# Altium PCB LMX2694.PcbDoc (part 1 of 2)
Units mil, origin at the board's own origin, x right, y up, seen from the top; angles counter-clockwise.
Board outline 2500 x 2200 mil, 4 copper layers (Top Layer, RF GND, Signal GND, Bottom Layer), stack 60.6 mil thick; 109 components, 60 nets, 306 pads, 206 vias.
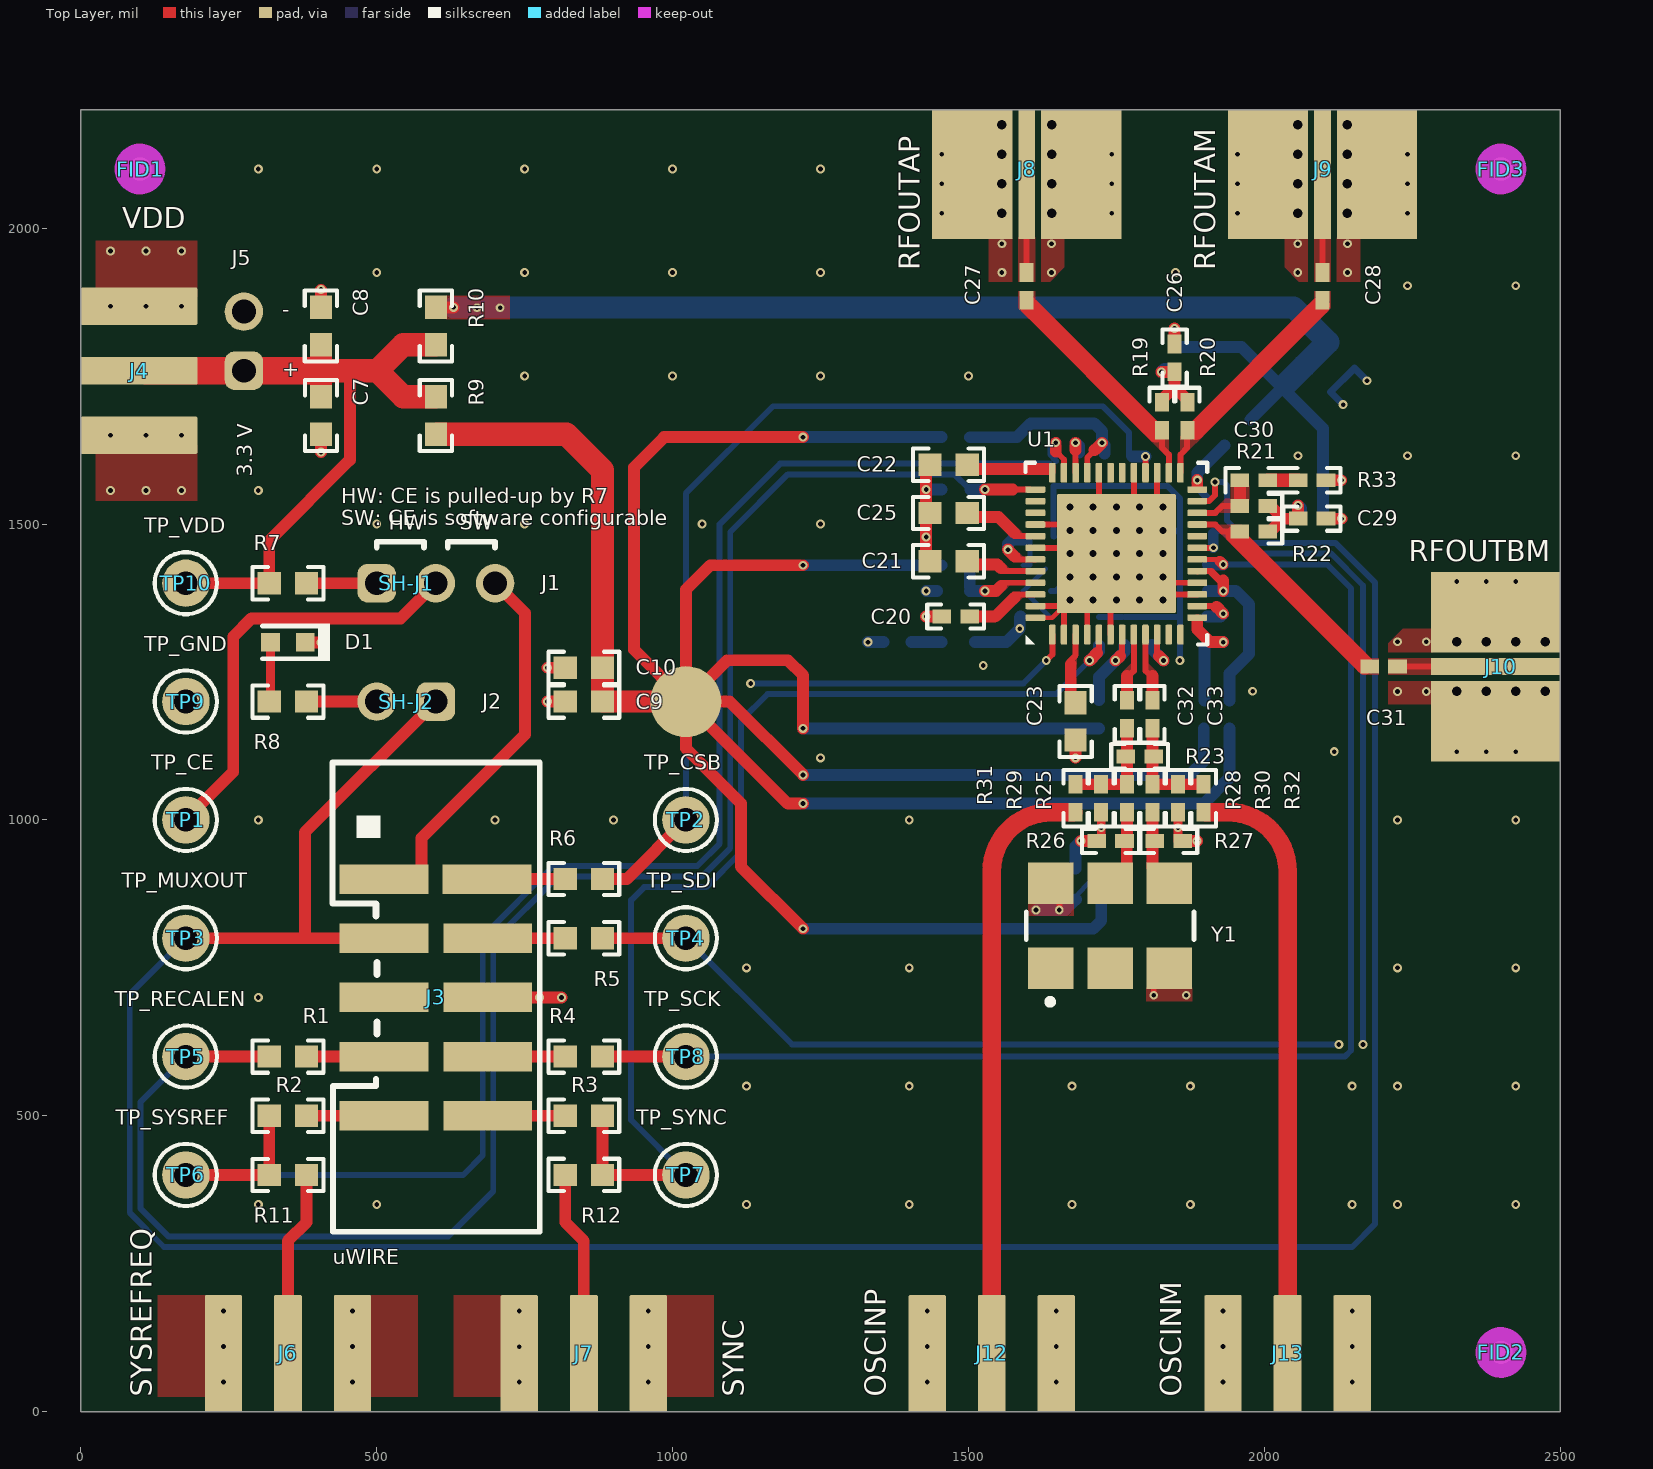
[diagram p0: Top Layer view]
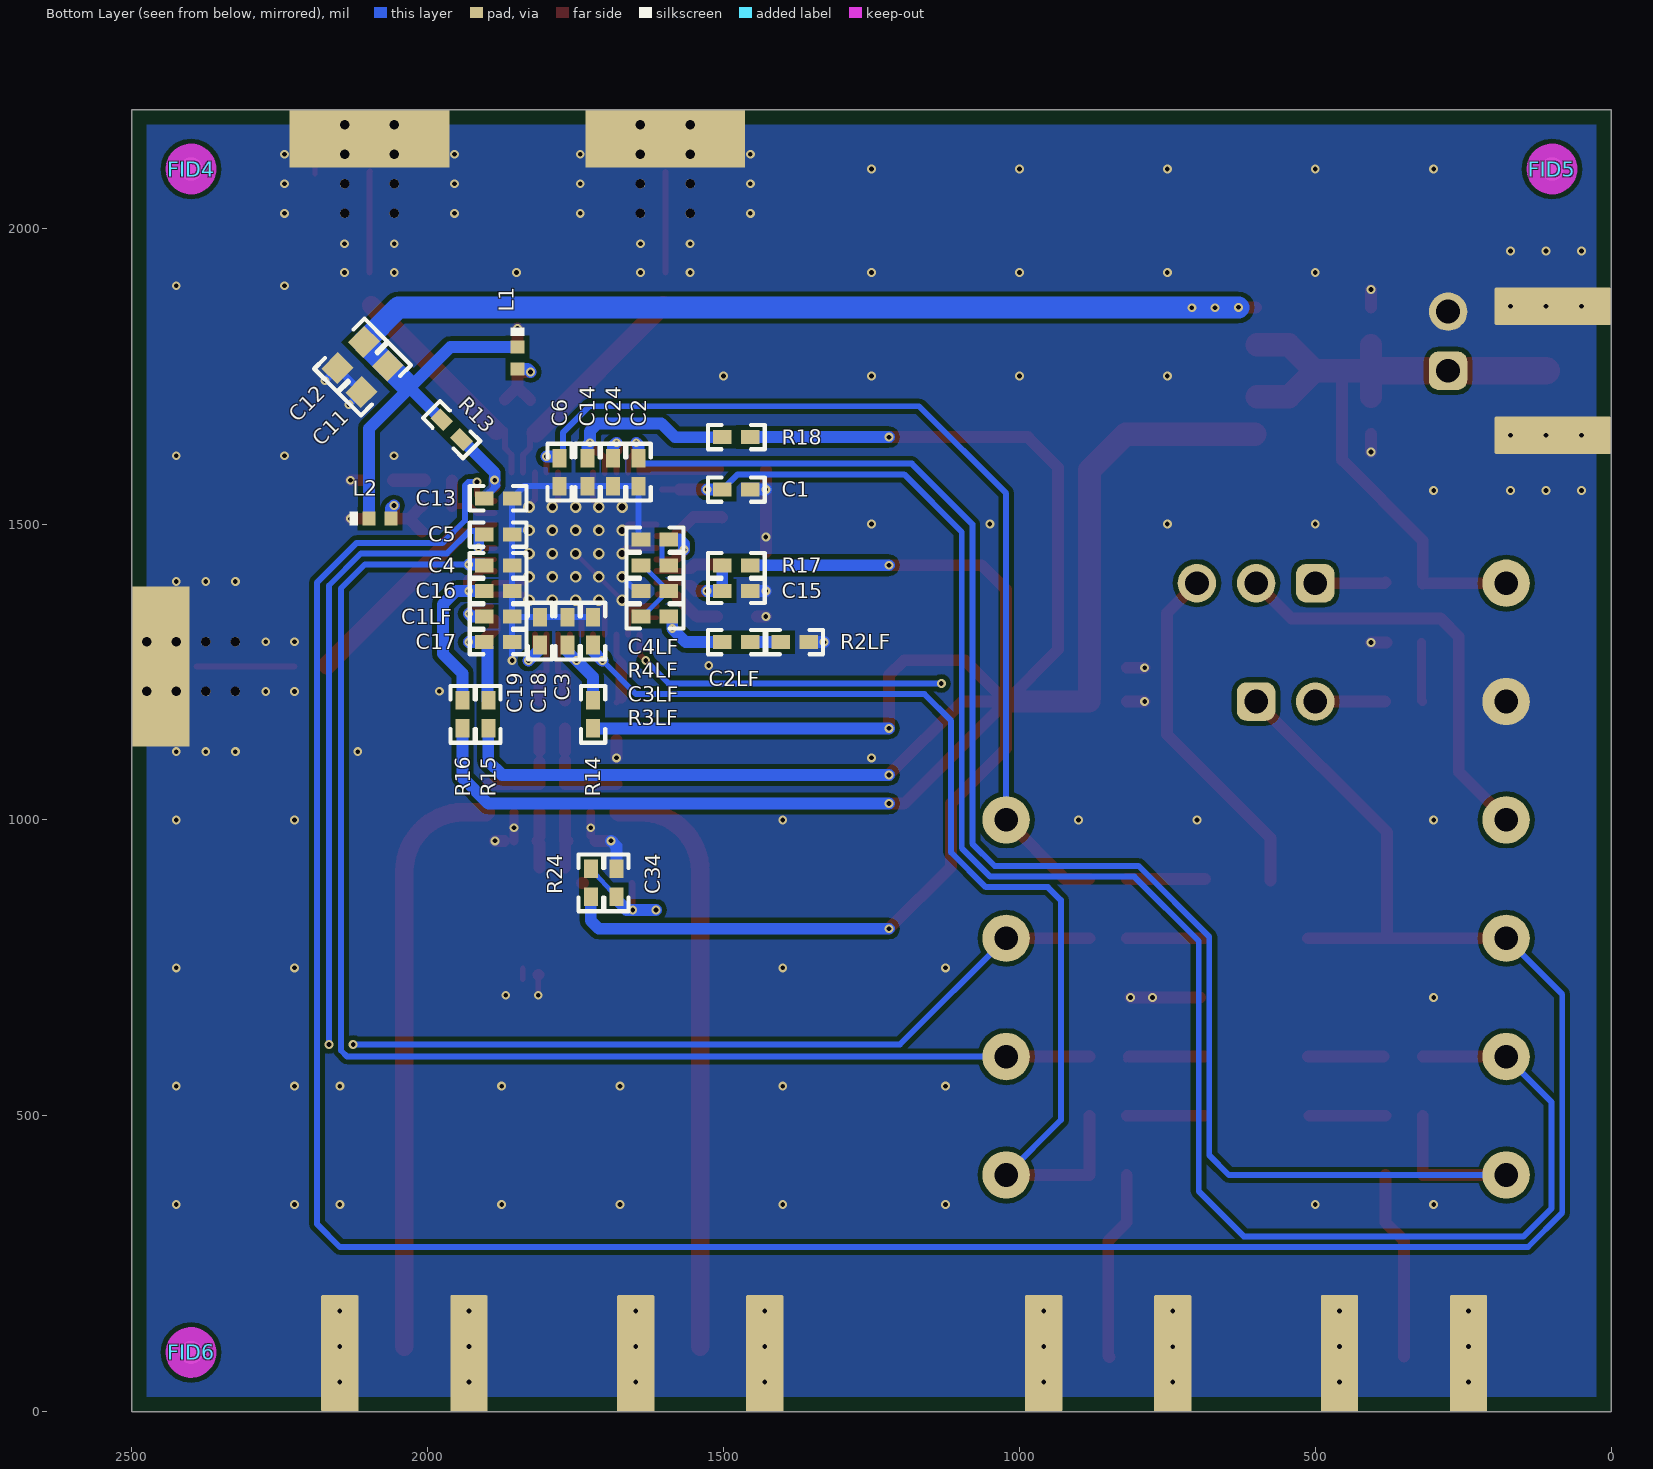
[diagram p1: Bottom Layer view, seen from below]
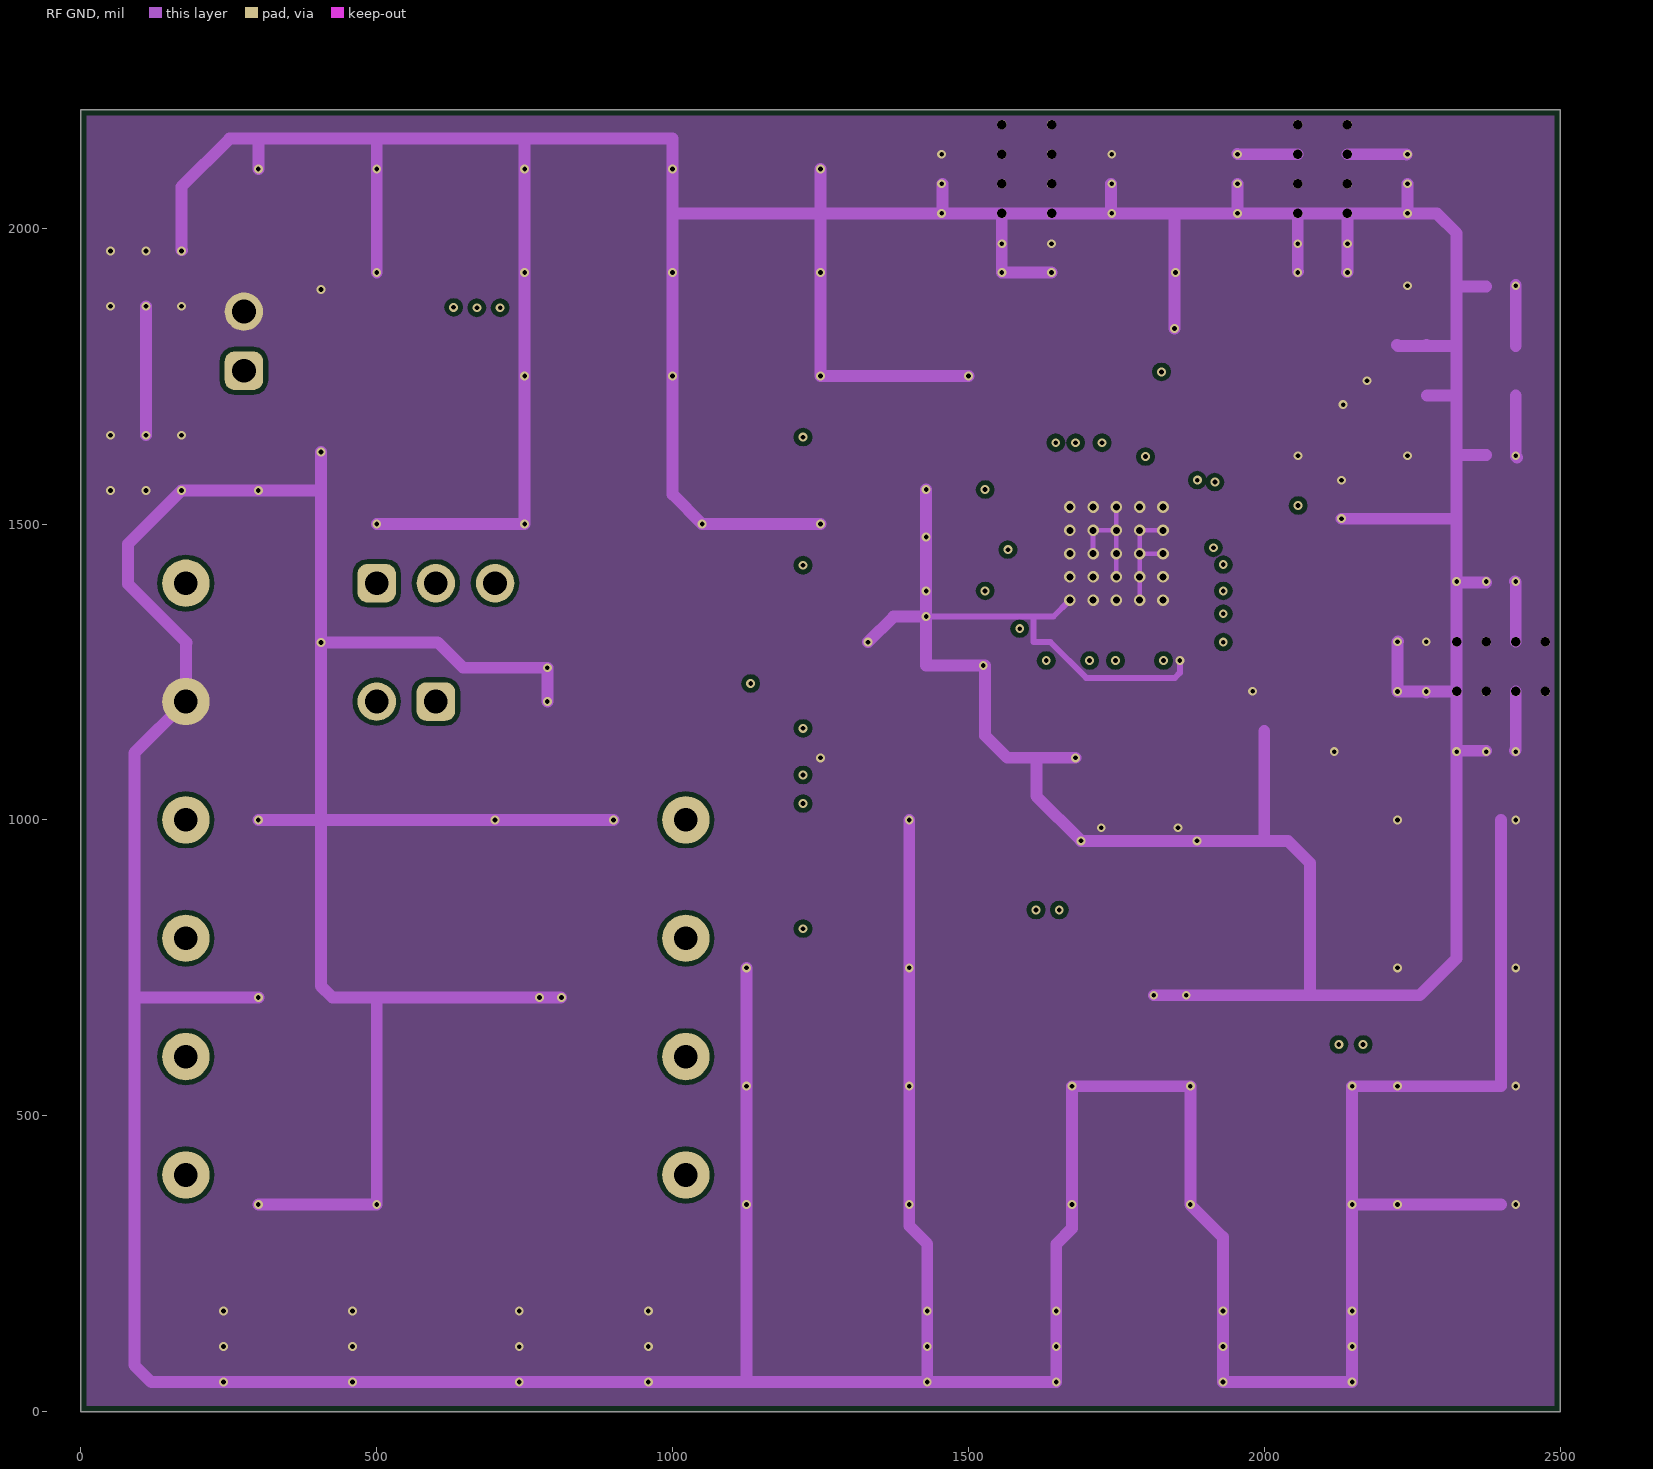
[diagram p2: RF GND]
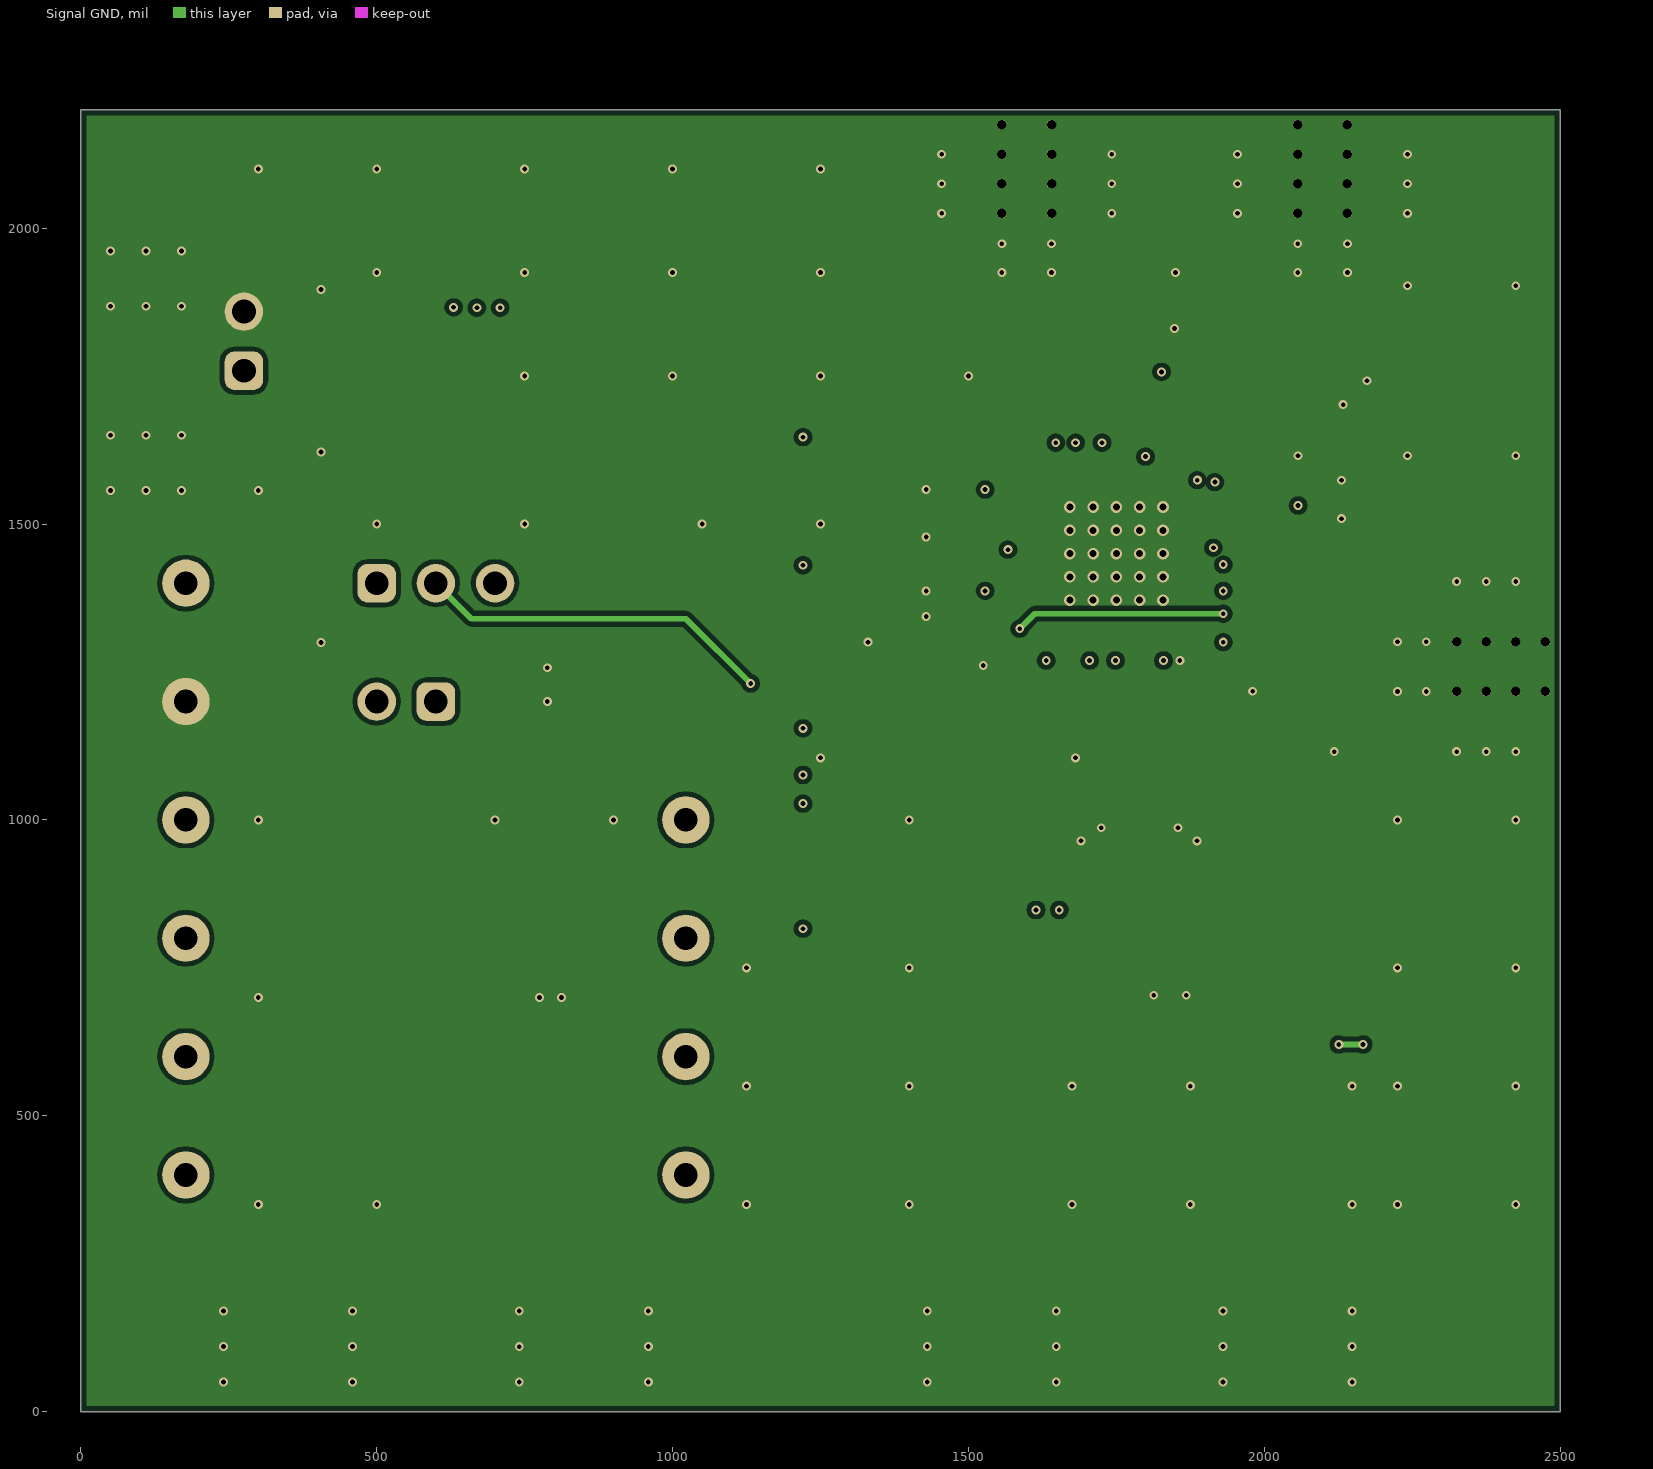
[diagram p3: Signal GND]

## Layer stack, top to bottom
Top Solder: solder mask 0.4, Solder Resist, Dk 3.5
Top Layer: signal copper 1.4
Dielectric1: core 16, Rogers RO4350B, Dk 3.66
RF GND: signal copper 1.4
Dielectric 2: dielectric 23, FR4, Dk 4.2
Signal GND: signal copper 1.4
Dielectric 3: dielectric 16, FR4, Dk 4.2
Bottom Layer: signal copper 1.4
Bottom Solder: solder mask 0.4, Solder Resist, Dk 3.5

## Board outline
0,0 0,2200 2500,2200 2500,0

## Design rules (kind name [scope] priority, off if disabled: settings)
AcuteAngle [All] p1: minimum=4.50000000000000E+0001 checktracksonly=FALSE
AssemblyTestPointUsage [All] p1: valid=2
BoardOutlineClearance BoardOutlineClearance_MountingHoles [OnCopper and InComponentClass('Mounting Holes')] p1: gap=39.37 ignorepadtopadclearanceinfootprint=FALSE
BoardOutlineClearance BoardOutlineClearance_Poly [OnCopper and IsPoly and not OnBottomLayer] p2: gap=25 ignorepadtopadclearanceinfootprint=FALSE except(10: Poly-OutlineEdge)
BoardOutlineClearance BoardOutlineClearance_Poly_Bottom [OnCopper and IsPoly and OnBottomLayer] p3: gap=25 ignorepadtopadclearanceinfootprint=FALSE
BoardOutlineClearance [OnCopper and Not InComponentClass('Logo') and not InComponentClass('FiducialMark') and not InRegion(1000,500,4000,800) and not InPoly and not InComponent('RFOUTAP')and not InComponent('RFOUTAM')and not InComponent('RFOUTBP')and not InComponent('RFOUTBM')and not InComponent('OSCINP')and not InComponent('OSCINM')and not InComponent('SYSREFREQ')and not InComponent('SYNC')and not InComponent('VDD')and not IsPad] p4: gap=75 ignorepadtopadclearanceinfootprint=FALSE except(25: Track-OutlineEdge Via-OutlineEdge)
Clearance Clearance_Keepouts [((IsTrack Or IsArc) And Not InPoly) And IsFree and IsKeepOut vs ((IsTrack Or IsArc) And Not InPoly) And IsFree and IsKeepOut] p1: gap=0 ignorepadtopadclearanceinfootprint=FALSE
Clearance Clearance_Poly [InPolygon] p2: gap=10 ignorepadtopadclearanceinfootprint=TRUE except(7.87: Arc-Fill Arc-Poly Arc-Region Track-Fill Track-Poly Track-Region SMDPad-Fill SMDPad-Poly SMDPad-Region THPad-Fill THPad-Poly THPad-Region Via-Fill Via-Poly Via-Region Fill-Fill Fill-Poly Fill-Region Poly-Poly Poly-Region Region-Region)
Clearance Clearance_FiducialMark [IsKeepOut and InComponentClass('FiducialMark') vs IsPad and InComponentClass('FiducialMark')] p3: gap=0 ignorepadtopadclearanceinfootprint=FALSE
Clearance [All] p4: gap=7.87 ignorepadtopadclearanceinfootprint=TRUE
ComponentClearance ComponentClearance_MountingHoles_FiducialMarks [InComponentClass('Mounting Holes') vs InComponentClass('FiducialMark')] p1: gap=50 collisioncheckmode=3 verticalgap=10 showdistances=FALSE
ComponentClearance ComponentClearance_Shunt [InComponentClass('Header') vs InComponentClass('Shunt')] p2: gap=0 collisioncheckmode=3 verticalgap=0 showdistances=FALSE
ComponentClearance ComponentClearance_Logo [InComponentClass('Logo')] p3: gap=50 collisioncheckmode=3 verticalgap=10 showdistances=FALSE
ComponentClearance ComponentClearance_ScrewToNut [(HasFootprint('NY PMS 440 0025 PH')) vs (HasFootprint('Keystone_1902C'))] p4: gap=5 collisioncheckmode=3 verticalgap=10 showdistances=FALSE
ComponentClearance ComponentClearance_MountingHoles [InComponentClass('Mounting Holes')] p5: gap=250 collisioncheckmode=3 verticalgap=100000 showdistances=FALSE
ComponentClearance ComponentClearance_SmallPassives [HasFootprint('0201*') or HasFootprint('0402*') or HasFootprint('0508') or HasFootprint('0603*') or HasFootprint('0612') or HasFootprint('0805*') or HasFootprint('0815*') or HasFootprint('0830*') or HasFootprint('1206*') or HasFootprint('1210*') or HasFootprint('1808*') or HasFootprint('1812*') or HasFootprint('1825*') or HasFootprint('2010*') or HasFootprint('2220*') or HasFootprint('2225*') or HasFootprint('2512*') or HasFootprint('2728*') or HasFootprint('3518*') vs HasFootprint('0201*') or HasFootprint('0402*') or HasFootprint('0508') or HasFootprint('0603*') or HasFootprint('0612') or HasFootprint('0805*') or HasFootprint('0815*') or HasFootprint('0830*') or HasFootprint('1206*') or HasFootprint('1210*') or HasFootprint('1808*') or HasFootprint('1812*') or HasFootprint('1825*') or HasFootprint('2010*') or HasFootprint('2220*') or HasFootprint('2225*') or HasFootprint('2512*') or HasFootprint('2728*') or HasFootprint('3518*')] p6: gap=14.96 collisioncheckmode=3 verticalgap=10 showdistances=FALSE
ComponentClearance ComponentClearance_THtoSMT [IsThruComponent vs IsSMTComponent] p7: gap=40 collisioncheckmode=3 verticalgap=30 showdistances=FALSE
ComponentClearance ComponentClearance_THtoTH [IsThruComponent vs IsThruComponent] p8: gap=30 collisioncheckmode=3 verticalgap=30 showdistances=FALSE
ComponentClearance [All] p9: gap=30 collisioncheckmode=3 verticalgap=10 showdistances=FALSE
DiffPairsRouting [All] p1: maxlimit=100 minlimit=10 mostfreqgap=10 toplayer_minwidth=15 toplayer_maxwidth=15 toplayer_prefwidth=15 midlayer1_minwidth=15 midlayer1_maxwidth=15 midlayer1_prefwidth=15 midlayer2_minwidth=15 midlayer2_maxwidth=15 midlayer2_prefwidth=15 bottomlayer_minwidth=15 bottomlayer_maxwidth=15 bottomlayer_prefwidth=15 maxuncoupledlength=1000
FabricationTestPointUsage TestPointUsage [All] p1: valid=2 allowmultiple=FALSE
FabricationTestpoint Testpoint [All] p1: side=3 testpointundercomponent=TRUE minsize=40 maxsize=100 preferedsize=60 minholesize=0 maxholesize=40 preferedholesize=32 testpointgrid=1 allowsidetop=TRUE allowsidebottom=TRUE usegrid=TRUE gridtolerance=0.01
FanoutControl Fanout_LCC [IsLCC] p1: bgadir=Out bgaviamode=Centered fanoutstyle=Auto fanoutdirection=Alternating viagrid=1 // Fanout_LCC (Default Rule)
FanoutControl Fanout_BGA [IsBGA] p2: bgadir=Out bgaviamode=Centered fanoutstyle=Auto fanoutdirection=Alternating viagrid=1 // Fanout_BGA (Default Rule)
FanoutControl Fanout_Default [All] p4: bgadir=Out bgaviamode=Centered fanoutstyle=Auto fanoutdirection=Alternating viagrid=1 // Fanout_Default (Default Rule)
FanoutControl Fanout_Small [(CompPinCount < 5)] p5: bgadir=Out bgaviamode=Centered fanoutstyle=Auto fanoutdirection=OutThenIn viagrid=1 // Fanout_Small (Default Rule)
HoleSize [All] p1: absolutevalues=TRUE maxlimit=251 minlimit=7.87 maxpercent=80.000 minpercent=20.000
MinimumAnnularRing MinimumAnnularRing_ThermalPadVias [IsVia and InAnyComponent] p1: minimumring=3.94
MinimumAnnularRing [All] p2: minimumring=3.5
MinimumSolderMaskSliver MinimumSolderMaskSliver_ThermalVia [IsVia vs IsPad] p1: minsoldermaskwidth=0.79
MinimumSolderMaskSliver MinimumSolderMaskSliver_Logo [InComponentClass('Logo') vs InComponentClass('Logo')] p2: minsoldermaskwidth=0.7
MinimumSolderMaskSliver [All] p3: minsoldermaskwidth=3.94
PlaneConnect [All] p1: planeconnectstyle=Direct reliefexpansion=10 reliefentries=4 reliefconductorwidth=10 reliefairgap=10
PolygonConnect [All] p1: connectstyle=Direct reliefconductorwidth=10 reliefentries=4 polygonreliefangle="90 Angle" airgapwidth=10
RoutingVias ThermalPadVias [IsVia and InAnyComponent] p1: holewidth=7.87 width=19.68 viastyle="Through Hole" minholewidth=7.87 minwidth=19.68 maxholewidth=12.99 maxwidth=23.62
RoutingVias [All] p2: holewidth=13 width=25 viastyle="Through Hole" minholewidth=8 minwidth=15 maxholewidth=18 maxwidth=25
SilkToBoardRegionClearance [Not ((IsComment or IsDesignator) And (Hide <> 'False')) and not InRegion(1000,500,4000,800)] p1:
SilkToSilkClearance SilkToSilkClearance_Pb-FreeLogo [(HasFootprint('Pb-Free_Overlay_Medium') OR HasFootprint('Pb-Free_Overlay_Small')) vs (HasFootprint('Pb-Free_Overlay_Medium') OR HasFootprint('Pb-Free_Overlay_Small'))] p1: silktosilkclearance=0
SilkToSilkClearance [All] p2: silktosilkclearance=3.94
SilkToSolderMaskClearance SilkToComponentPadClearance [(IsPad or IsFill or IsRegion) and InAnycomponent] p1: minsilkscreentomaskgap=3.94 clearancetoexposedcopper=TRUE
SilkToSolderMaskClearance "Silk to Solder Mask Opening" [All] p2: minsilkscreentomaskgap=3 clearancetoexposedcopper=FALSE
SolderMaskExpansion [All] p1: expansion=1.97
Width [All] p1: maxlimit=100 minlimit=6 preferedwidth=10 checkconnectedcopper=TRUE
15 further rules are at their usual default settings.

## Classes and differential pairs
component class FiducialMark: FID1 FID2 FID3 FID4 FID5 FID6
component class LMX2694_HW: FID1 FID2 FID3 FID4 FID5 FID6 SH-J1 SH-J2
component class Header: J1 J2 J5
component class LMX2694_SYNTH: C1LF C2LF C3LF C4LF C13 C14 C15 C16 C17 C18 C19 C20 C21 C22 C23 C24 C25 C26 C27 C28 C29 C30 C31 C32 C33 C34 J8 J9 J10 J12 J13 L1 L2 R2LF R3LF R4LF R13 R14 R15 R16 R17 R18 R19 R20 R21 R22 R23 R24 R25 R26 R27 R28 R29 R30 R31 R32 R33 U1 Y1
component class Shunt: SH-J1 SH-J2

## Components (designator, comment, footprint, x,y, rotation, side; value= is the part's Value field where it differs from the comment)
C1 "885012005044" 0402 1478.35,1558.27 r180 bottom value=47pF
C1LF "C0402C471K5GAC7867" 0402 1880.91,1343.7 r180 bottom value=470pF
C2 "885012005044" 0402 1643.5,1587.6 r270 bottom value=47pF
C2LF "CGA2B3X7R1H683K050BB" 0402 1478.35,1300.39 r180 bottom value=0.068uF
C3 "885012005044" 0402 1720.47,1319.09 r90 bottom value=47pF
C3LF "885012005044" 0402 1615.94,1387.01 r0 bottom value=47pF
C4 "885012005044" 0402 1880.91,1430.32 r180 bottom value=47pF
C4LF "C0402C182J5RACTU" 0402 1615.94,1473.62 r0 bottom value=1800pF
C5 "885012005044" 0402 1880.91,1482.09 r180 bottom value=47pF
C6 "885012005044" 0402 1776.97,1587.6 r270 bottom value=47pF
C7 "885012206046" 0603 405.71,1683.46 r270 top value=0.1uF
C8 "GRM188R61A106KAALD" 0603 405.71,1834.65 r90 top value=10uF
C9 "885012206046" 0603 850,1200 r180 top value=0.1uF
C10 "GRM188R61A106KAALD" 0603 850,1257.09 r180 top value=10uF
C11 "885012206046" 0603 2089.79,1745.25 r315 bottom value=0.1uF
C12 "GRM188R61A106KAALD" 0603 2130.09,1785.66 r315 bottom value=10uF
C13 "885012205037" 0402 1880.91,1543.5 r180 bottom value=0.1uF
C14 "GRM155R61E105KA12D" 0402 1730.12,1587.6 r270 bottom value=1uF
C15 "GRM155R61E105KA12D" 0402 1478.35,1387.01 r180 bottom value=1uF
C16 "GRM155R61E105KA12D" 0402 1880.91,1387.01 r180 bottom value=1uF
C17 "GRM155R61E105KA12D" 0402 1880.91,1300.39 r180 bottom value=1uF
C18 "GRM155R61E105KA12D" 0402 1763.78,1319.09 r90 bottom value=1uF
C19 "GRM155R61E105KA12D" 0402 1810.04,1319.09 r90 bottom value=1uF
C20 "GRM155R61E105KA12D" 0402 1478.35,1343.7 r180 top value=1uF
C21 "GRM188R61A106KAALD" 0603 1466.54,1437.2 r180 top value=10uF
C22 "GRM188R61A106KAALD" 0603 1466.54,1600.2 r180 top value=10uF
C23 "GRM188R61A106KAALD" 0603 1681.1,1166.54 r270 top value=10uF
C24 "GRM155R61E105KA12D" 0402 1686.81,1587.6 r270 bottom value=1uF
C25 "GRM188R61A106KAALD" 0603 1466.54,1518.7 r180 top value=10uF
C26 "520L103KT16T" 0402_065 1848.43,1780.71 r270 top value=0.01uF
C27 "520L103KT16T" 0402_065 1598.43,1901.57 r270 top value=0.01uF
C28 "520L103KT16T" 0402_065 2098.43,1901.57 r270 top value=0.01uF
C29 "520L103KT16T" 0402_065 2080.71,1509.06 r180 top value=0.01uF
C30 "520L103KT16T" 0402_065 1982.28,1574.02 r180 top value=0.01uF
C31 "520L103KT16T" 0402_065 2201.57,1259.06 r180 top value=0.01uF
C32 "885012205037" 0402 1767.72,1178.35 r270 top value=0.1uF
C33 "885012205037" 0402 1811.02,1178.35 r270 top value=0.1uF
C34 "GRM155R61E105KA12D" 0402 1681.1,893.7 r90 bottom value=1uF
D1 "LTST-C190GKT" LED_LTST-C190 350,1300 r0 top value=Green
FID1 "Fiducial" Fiducial10-20 100,2100 r0 top
FID2 "Fiducial" Fiducial10-20 2400,100 r0 top
FID3 "Fiducial" Fiducial10-20 2400,2100 r0 top
FID4 "Fiducial" Fiducial10-20 2400,2100 r180 bottom
FID5 "Fiducial" Fiducial10-20 100,2100 r180 bottom
FID6 "Fiducial" Fiducial10-20 2400,100 r180 bottom
J1 "TSW-103-07-G-S" TSW-103-07-G-S 600,1400 r0 top
J2 "TSW-102-07-G-S" TSW-102-07-G-S 550,1200 r180 top
J3 "uWIRE" FCI_52601-S10-8LF 600,700 r0 top
J4 "VDD" FP-CON-SMA-EDGE-S_CONN_JACK-MFG -187.5,1759.06 r90 top
J5 "TSW-102-07-G-S" TSW-102-07-G-S 275.59,1809.06 r90 top
J6 "SYSREFREQ" FP-CON-SMA-EDGE-S_CONN_JACK-MFG 350,-187.5 r180 top
J7 "SYNC" FP-CON-SMA-EDGE-S_CONN_JACK-MFG 850,-187.5 r180 top
J8 "RFOUTAP" Johnson_142-0771-831 1598.43,2200 r0 top
J9 "RFOUTAM" Johnson_142-0771-831 2098.43,2200 r0 top
J10 "RFOUTBM" Johnson_142-0771-831 2500,1259.06 r270 top
J12 "OSCINP" FP-CON-SMA-EDGE-S_CONN_JACK-MFG 1539.37,-187.5 r180 top
J13 "OSCINM" FP-CON-SMA-EDGE-S_CONN_JACK-MFG 2039.37,-187.5 r180 top
L1 "LQG15HS18NJ02D" IND_LQG15H 1848.43,1780.71 r270 bottom value=18nH
L2 "LQG15HS18NJ02D" IND_LQG15H 2080.71,1509.06 r180 bottom value=18nH
R1 "CRCW060333R0JNEA" 0603 350,600 r0 top value=33
R2 "CRCW060333R0JNEA" 0603 350,500 r180 top value=33
R2LF "CRCW040268R1FKED" 0402 1379.92,1300.39 r0 bottom value=68.1
R3 "CRCW060333R0JNEA" 0603 850,500 r0 top value=33
R3LF "CRCW04020000Z0ED" 0402 1615.94,1343.7 r0 bottom value=0
R4 "CRCW060333R0JNEA" 0603 850,600 r0 top value=33
R4LF "CRCW040218R2FKED" 0402 1615.94,1430.32 r180 bottom value=18.2
R5 "CRCW060333R0JNEA" 0603 850,800 r0 top value=33
R6 "CRCW060333R0JNEA" 0603 850,900 r0 top value=33
R7 "CRCW06031K00JNEA" 0603 350,1400 r180 top value=1.0k
R8 "CRCW0603330RJNEA" 0603 350,1200 r180 top value=330
R9 "CRCW06030000Z0EA" 0603 600,1683.46 r270 top value=0
R10 "CRCW06030000Z0EA" 0603 600,1834.65 r90 top value=0
R11 "CRCW06030000Z0EA" 0603 350,400 r180 top value=0
R12 "CRCW06030000Z0EA" 0603 850,400 r0 top value=0
R13 "CRCW04020000Z0ED" 0402 1959.65,1659.65 r225 bottom value=0
R14 "CRCW04020000Z0ED" 0402 1720.47,1178.35 r90 bottom value=0
R15 "CRCW04020000Z0ED" 0402 1897.64,1178.35 r90 bottom value=0
R16 "CRCW04020000Z0ED" 0402 1940.94,1178.35 r90 bottom value=0
R17 "CRCW04020000Z0ED" 0402 1478.35,1430.32 r0 bottom value=0
R18 "CRCW04020000Z0ED" 0402 1478.35,1646.85 r0 bottom value=0
R19 "FC0402E50R0BST1" 0402 1826.77,1682.28 r90 top value=50
R20 "FC0402E50R0BST1" 0402 1870.08,1682.28 r90 top value=50
R21 "FC0402E50R0BST1" 0402 1982.28,1530.71 r0 top value=50
R22 "FC0402E50R0BST1" 0402 1982.28,1487.4 r0 top value=50
R23 "CRCW0402100RFKED" 0402 1789.37,1107.48 r180 top value=100
R24 "CRCW040210R0FKED" 0402 1724.41,893.7 r90 bottom value=10.0
R25 "CRCW04020000Z0ED" 0402 1767.72,1036.61 r90 top value=0
R26 "CRCW0402140RFKED" 0402 1740.16,964.57 r180 top value=140
R27 "CRCW0402140RFKED" 0402 1838.58,964.57 r0 top value=140
R28 "CRCW04020000Z0ED" 0402 1811.02,1036.61 r270 top value=0
R29 "CRCW040249R9FKED" 0402 1724.41,1036.61 r90 top value=49.9
R30 "CRCW040249R9FKED" 0402 1854.33,1036.61 r90 top value=49.9
R31 "CRCW04020000Z0ED" 0402 1681.1,1036.61 r270 top value=0
R32 "CRCW04020000Z0ED" 0402 1897.64,1036.61 r270 top value=0
R33 "FC0402E50R0BST1" 0402 2080.71,1574.02 r180 top value=50
SH-J1 "SNT-100-BK-G" SNT-100-BK-G 550,1400 r180 top value=1x2
SH-J2 "SNT-100-BK-G" SNT-100-BK-G 550,1200 r180 top value=1x2
TP1 "TP_CE" Keystone5002 177.5,1000 r0 top
TP2 "TP_CSB" Keystone5002 1022.5,1000 r0 top
TP3 "TP_MUXOUT" Keystone5002 177.5,800 r0 top
TP4 "TP_SDI" Keystone5002 1022.5,800 r0 top
TP5 "TP_RECALEN" Keystone5002 177.5,600 r0 top
TP6 "TP_SYSREF" Keystone5002 177.5,400 r0 top
TP7 "TP_SYNC" Keystone5002 1022.5,400 r0 top
TP8 "TP_SCK" Keystone5002 1022.5,600 r0 top
TP9 "TP_GND" Keystone5001 177.5,1200 r0 top
TP10 "TP_VDD" Keystone5000 177.5,1400 r0 top
U1 "LMX2694-EP" RTC0048A 1750,1450 r90 top
Y1 "100MHz" Vectron_VC-708 1739.37,821.26 r90 top

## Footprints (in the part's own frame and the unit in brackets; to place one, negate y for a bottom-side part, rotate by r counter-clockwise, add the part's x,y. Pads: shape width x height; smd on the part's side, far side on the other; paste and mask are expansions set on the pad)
0402 [mm] "0402 from SM-752 data"
  rect 0.8x0.6 smd: 1(-0.6,0) 2(0.6,0)
  silkscreen extent -1.22,-0.52 1.22,0.52, body extent -0.55,-0.3 0.55,0.3, height 0.6
0402_065 [mm] "0402"
  rect 0.8x0.6 smd: 1(-0.6,0) 2(0.6,0)
  silkscreen extent -1.22,-0.52 1.22,0.52, body extent -0.55,-0.3 0.55,0.3, height 0.65
0603 [mm] "0603 from SM-752 data"
  rect 1x0.95 smd: 1(-0.8,0) 2(0.8,0)
  silkscreen extent -1.52,-0.69 1.52,0.69, body extent -0.87,-0.47 0.87,0.47, height 1
FCI_52601-S10-8LF [mil] "FCI Electronics"
  rect 150x50 smd: 1(-87.5,200) 2(86.5,200) 3(-87.5,100) 4(87.5,100) 5(-87.5,0) 6(87.5,0) 7(-87.5,-100) 8(87.5,-100) 9(-87.5,-200) 10(87.5,-200)
  silkscreen extent -174,-396 176,397, body extent -172,-395 173,395, height 496
Fiducial10-20 [mm]
  round 1 smd mask+0.5: 1(0,0)
  Top Layer keep-out circle w1.178: c0,0 r0.5
FP-CON-SMA-EDGE-S_CONN_JACK-MFG [mm]
  rrect8% 1.2x5 smd paste+0 mask+0: 1(0,-7.26)
  rrect6% 1.6x5 smd paste+0 mask+0: 2(-2.77,-7.26) 3(2.77,-7.26)
  rrect6% 1.6x5 smd far side paste+0 mask+0: 4(-2.77,-7.26) 5(2.77,-7.26)
  body extent -3.27,-9.86 3.27,4.86, height 0.25
IND_LQG15H [mm] "MuRata"
  rect 0.55x0.6 smd: 1(-0.475,0) 2(0.475,0)
  silkscreen extent -1.3,-0.3 -0.95,0.3, body extent -0.52,-0.27 0.52,0.27, height 0.55
Johnson_142-0771-831 [mil] "JACK, SMA, 50 Ohm, Gold, Edge Mount"
  rect 28.5x218 smd: 1(0,-109)
  rect 135.75x218 smd: 2(-92.12,-109) 3(92.13,-109)
  round 16 hole 16: 2(-42,-175) 2(-42,-125) 2(-42,-75) 2(-42,-25) 3(42,-175) 3(42,-125) 3(42,-75) 3(42,-25)
  rect 270x97.5 smd far side: 4(0,-48.75)
  body extent -124,-179 123,375, height 131
Keystone5000 [mil] "For Keystone 500x miniature loop terminals"
  round 80 hole 40: 1(0,0)
  silkscreen extent -52,-52 52,52, body extent -49,-49 49,49, height 182
Keystone5001 [mil] "For Keystone 500x miniature loop terminals"
  round 80 hole 40: 1(0,0)
  silkscreen extent -52,-52 52,52, body extent -49,-49 49,49, height 182
Keystone5002 [mil] "For Keystone 500x miniature loop terminals"
  round 80 hole 40: 1(0,0)
  silkscreen extent -52,-52 52,52, body extent -49,-49 49,49, height 182
LED_LTST-C190 [mm] "Lite-On"
  rect 0.8x0.8 smd: 1(-0.75,0) 2(0.75,0)
  silkscreen extent -1.1,-0.8 1.8,0.8, body extent -0.85,-0.45 0.85,0.45, height 0.9
RTC0048A [mm] "PVQFN, 64-Leads, Body 7x7mm, Pitch 0.5mm"
  rrect36% 0.85x0.28 smd paste-0.28: 1(-3.475,2.75) 2(-3.475,2.25) 3(-3.475,1.75) 4(-3.475,1.25) 5(-3.475,0.75) 6(-3.475,0.25) 7(-3.475,-0.25) 8(-3.475,-0.75) 9(-3.475,-1.25) 10(-3.475,-1.75) 11(-3.475,-2.25) 12(-3.475,-2.75) 25(3.475,-2.75) 26(3.475,-2.25) 27(3.475,-1.75) 28(3.475,-1.25) 29(3.475,-0.75) 30(3.475,-0.25) 31(3.475,0.25) 32(3.475,0.75) 33(3.475,1.25) 34(3.475,1.75) 35(3.475,2.25) 36(3.475,2.75)
  rrect36% 0.28x0.85 smd paste-0.28: 13(-2.75,-3.475) 14(-2.25,-3.475) 15(-1.75,-3.475) 16(-1.25,-3.475) 17(-0.75,-3.475) 18(-0.25,-3.475) 19(0.25,-3.475) 20(0.75,-3.475) 21(1.25,-3.475) 22(1.75,-3.475) 23(2.25,-3.475) 24(2.75,-3.475) 37(2.75,3.475) 38(2.25,3.475) 39(1.75,3.475) 40(1.25,3.475) 41(0.75,3.475) 42(0.25,3.475) 43(-0.25,3.475) 44(-0.75,3.475) 45(-1.25,3.475) 46(-1.75,3.475) 47(-2.25,3.475) 48(-2.75,3.475)
  rrect2% 5.1x5.1 smd paste-5.1: 49(0,0)
  body extent -3.55,-3.55 3.55,3.55, height 0.9
SNT-100-BK-G [mil] "Samtec STEP model"
  round 1 on Mech3: 0(0,0)
  body extent -100,-50 100,50, height 344
TSW-102-07-G-S [mm] "Samtec 100mil, 1x2, 230 mil above insulator"
  rrect50% 1.65x1.65 hole 1.016: 1(-1.27,0)
  round 1.65 hole 1.016: 2(1.27,0)
  body extent -2.54,-1.27 2.54,1.27, height 8.38
TSW-103-07-G-S [mm] "Samtec 100mil, 1x3, 230 mil above insulator"
  rrect50% 1.65x1.65 hole 1.016: 1(-2.54,0)
  round 1.65 hole 1.016: 2(0,0) 3(2.54,0)
  body extent -3.81,-1.27 3.81,1.27, height 8.38
Vectron_VC-708 [mm] "SMD, 6-Leads, Body 5x7mm, Pitch 2.54mm"
  rect 1.78x1.96 smd: 1(-1.83,2.54) 2(-1.83,0) 3(-1.83,-2.54) 4(1.83,-2.54) 5(1.83,0) 6(1.83,2.54)
  silkscreen extent -3.39,-3.6 0.6,3.6, body extent -2.58,-3.57 2.58,3.57, height 1.8

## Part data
C1 C2 C3 C3LF C4 C5 C6: library part CMP-0006214-2, "CAP, CERM, 47 pF, 50 V, +/- 5%, C0G/NP0, 0402", Cap_Case=0402, Manufacturer="Wurth Elektronik", Supplier Part Number 1=732-7459-1-ND, TempCo=C0G/NP0, Tolerance_%=5%, Value1=Unknown, Value2=50V, ValueDisplayed=47pF
C1LF: library part CMP-0860150-1, "CAP, CERM, 470 pF, 50 V,+/- 10%, C0G/NP0, 0402", Cap_Case=0402, Manufacturer=Kemet, TempCo=C0G/NP0, Tolerance_%=10%, Value2=50V, ValueDisplayed=470pF
C2LF: library part CMP-0006331-2, "CAP, CERM, 0.068 uF, 50 V, +/- 10%, X7R, AEC-Q200 Grade 1, 0402", Cap_Case=0402, Manufacturer=TDK, Supplier Part Number 1=445-6898-1-ND, TempCo=X7R, Tolerance_%=10%, Value1="0.05606 ohm", Value2=50V, ValueDisplayed=68nF
C4LF: library part CMP-0080631-1, "CAP, CERM, 1800 pF, 50 V,+/- 5%, X7R, 0402", Cap_Case=0402, Manufacturer=Kemet, Supplier Part Number 1=399-8953-1-ND, TempCo=X7R, Tolerance_%=5%, Value2=50V, ValueDisplayed=1.8nF
C7 C9 C11: library part CMP-0006829-4, "CAP, CERM, 0.1 uF, 16 V, +/- 10%, X7R, 0603", Cap_Case=0603, Manufacturer="Wurth Elektronik", Supplier Part Number 1=710-885012206046, TempCo=X7R, Tolerance_%=10%, Value1=Unknown, Value2=16V, ValueDisplayed=0.1µF
C8 C10 C12 C21 C22 C23 C25: library part CMP-0086193-1, "CAP, CERM, 10 µF, 10 V,+/- 10%, X5R, 0603", Cap_Case=0603, Manufacturer=MuRata, TempCo=X5R, Tolerance_%=10%, Value2=10V, ValueDisplayed=10µF
C13 C32 C33: library part CMP-0006228-2, "CAP, CERM, 0.1 uF, 16 V, +/- 10%, X7R, 0402", Cap_Case=0402, Manufacturer="Wurth Elektronik", Supplier Part Number 1=732-7532-1-ND, TempCo=X7R, Tolerance_%=10%, Value1=Unknown, Value2=16V, ValueDisplayed=0.1µF
C14 C15 C16 C17 C18 C19 C20 C24 C34: library part CMP-0006608-2, "CAP, CERM, 1 uF, 25 V, +/- 10%, X5R, 0402", Cap_Case=0402, Manufacturer=MuRata, Supplier Part Number 1=490-10017-1-ND, TempCo=X5R, Tolerance_%=10%, Value1=Unknown, Value2=25V, ValueDisplayed=1µF
C26 C27 C28 C29 C30 C31: library part CMP-0006210-2, "CAP, CERM, 0.01 uF, 16 V, +/- 10%, X7R, 0402", Cap_Case=0402, Manufacturer="AT Ceramics", Supplier Part Number 1=1284-1540-1-ND, TempCo=X7R, Tolerance_%=10%, Value1=Unknown, Value2=16V, ValueDisplayed=10nF
D1: library part CMP-0002827-3, "LED, Green, SMD", Color=green, Manufacturer=Lite-On, Power_TotalModule=100mW, Value1=0.1W, Value2=2.1V
FID1 FID2 FID3 FID4 FID5 FID6: library part CMP-0077181-1, "Fiducial mark.  There is nothing to buy or mount.", Manufacturer=N/A
J1: library part CMP-0075407-2, "Header, 100mil, 3x1, Gold, TH", Color=Black, Current_A=6.3A, Manufacturer=Samtec, Supplier Part Number 1=SAM1029-03-ND, Voltage_V=550V
J2 J5: library part CMP-0075405-2, "Header, 100mil, 2x1, Gold, TH", Color=Black, Current_A=6.3A, Manufacturer=Samtec, Supplier Part Number 1=SAM1029-02-ND, Voltage_V=550V
J3: library part CMP-0055434-2, "Header (shrouded), 100mil, 5x2, Gold, SMT", Manufacturer=FCI, PartNumber=52601-S10-8LF, Supplier Part Number 1=609-3593-ND
J4 J6 J7 J12 J13: library part CMP-0088000-3, "CONN SMA JACK STR EDGE MNT", Manufacturer="RF Solutions Ltd.", PartNumber=CON-SMA-EDGE-S
J8 J9 J10: library part CMP-0055844-2, "JACK, SMA, 50 Ohm, Gold, Edge Mount", Color=Gold, Manufacturer="Cinch Connectivity", PartNumber=142-0771-831, Supplier Part Number 1=J808-ND, Voltage_V=170V
L1 L2: library part CMP-0058614-1, "Inductor, Multilayer, Air Core, 18 nH, 0.3 A, 0.36 ohm, SMD", Manufacturer=MuRata, Supplier Part Number 1=490-2626-1-ND, Value1="0.36 ohm", Value2=0.3A, ValueDisplayed=18nH
R1 R2 R3 R4 R5 R6: library part CMP-0025787-4, "RES, 33, 5%, 0.1 W, AEC-Q200 Grade 0, 0603", Manufacturer=Vishay-Dale, Power_W=100mW, Supplier Part Number 1=541-33GCT-ND, TempCo="200 ppm/C", Tolerance_%=5%, Value2=0.1W, Value_Code=33R0, ValueDisplayed=33
R2LF: library part CMP-0026507-2, "RES, 68.1, 1%, 0.063 W, AEC-Q200 Grade 0, 0402", Manufacturer=Vishay-Dale, Power_W=63mW, Supplier Part Number 1=541-68.1LCT-ND, TempCo="100 ppm/C", Tolerance_%=1%, Value2=0.063W, Value_Code=68R1, ValueDisplayed=68.1
R3LF R13 R14 R15 R16 R17 R18 R25 R28 R31 R32: library part CMP-0026822-3, "RES, 0, 5%, 0.063 W, AEC-Q200 Grade 0, 0402", Manufacturer=Vishay-Dale, Power_W=63mW, Supplier Part Number 1=541-0.0JCT-ND, TempCo="200 ppm/C", Tolerance_%=5%, Value2=0.063W, Value_Code=0000, ValueDisplayed=0
R4LF: library part CMP-0026061-3, "RES, 18.2, 1%, 0.063 W, AEC-Q200 Grade 0, 0402", Manufacturer=Vishay-Dale, Power_W=63mW, Supplier Part Number 1=541-18.2LCT-ND, TempCo="100 ppm/C", Tolerance_%=1%, Value2=0.063W, Value_Code=18R2, ValueDisplayed=18.2
R7: library part CMP-0025729-4, "RES, 1.0 k, 5%, 0.1 W, AEC-Q200 Grade 0, 0603", Manufacturer=Vishay-Dale, Power_W=100mW, Supplier Part Number 1=541-1.0KGCT-ND, TempCo="200 ppm/C", Tolerance_%=5%, Value2=0.1W, Value_Code=1k00, ValueDisplayed=1.0k
R8: library part CMP-0025785-4, "RES, 330, 5%, 0.1 W, AEC-Q200 Grade 0, 0603", Manufacturer=Vishay-Dale, Power_W=100mW, Supplier Part Number 1=541-330GCT-ND, TempCo="200 ppm/C", Tolerance_%=5%, Value2=0.1W, Value_Code=330R, ValueDisplayed=330
R9 R10 R11 R12: library part CMP-0025697-4, "RES, 0, 5%, 0.1 W, AEC-Q200 Grade 0, 0603", Manufacturer=Vishay-Dale, Power_W=100mW, Supplier Part Number 1=541-0.0GCT-ND, TempCo="200 ppm/C", Tolerance_%=5%, Value2=0.1W, Value_Code=0000, ValueDisplayed=0
R19 R20 R21 R22 R33: library part CMP-0026791-1, "RES, 50, 0.1%, 0.05 W, 0402", Manufacturer=Vishay-Dale, Power_W=50mW, Supplier Part Number 1=FC0402-50BWCT-ND, TempCo="25 ppm/C", Tolerance_%=0.1%, Value2=0.05W, Value_Code=50R0, ValueDisplayed=50
R23: library part CMP-0025951-3, "RES, 100, 1%, 0.063 W, AEC-Q200 Grade 0, 0402", Manufacturer=Vishay-Dale, Power_W=63mW, Supplier Part Number 1=541-100LCT-ND, TempCo="100 ppm/C", Tolerance_%=1%, Value2=0.063W, Value_Code=100R, ValueDisplayed=100
R24: library part CMP-0025963-3, "RES, 10.0, 1%, 0.063 W, AEC-Q200 Grade 0, 0402", Manufacturer=Vishay-Dale, Power_W=63mW, Supplier Part Number 1=541-10.0LCT-ND, TempCo="100 ppm/C", Tolerance_%=1%, Value2=0.063W, Value_Code=10R0, ValueDisplayed=10.0
R26 R27: library part CMP-0026010-3, "RES, 140, 1%, 0.063 W, AEC-Q200 Grade 0, 0402", Manufacturer=Vishay-Dale, Power_W=63mW, Supplier Part Number 1=541-140LCT-ND, TempCo="100 ppm/C", Tolerance_%=1%, Value2=0.063W, Value_Code=140R, ValueDisplayed=140
R29 R30: library part CMP-0026404-2, "RES, 49.9, 1%, 0.063 W, AEC-Q200 Grade 0, 0402", Manufacturer=Vishay-Dale, Power_W=63mW, Supplier Part Number 1=541-49.9LCT-ND, TempCo="100 ppm/C", Tolerance_%=1%, Value2=0.063W, Value_Code=49R9, ValueDisplayed=49.9
SH-J1 SH-J2: library part CMP-0003623-3, "Shunt, 100mil, Gold plated, Black", Alternate Manufacturer=3M, Alternate PartNumber=969102-0000-DA, Manufacturer=Samtec, Supplier Part Number 1=SAM8858-ND
TP1 TP2 TP3 TP4 TP5 TP6 TP7 TP8: library part CMP-0055139-1, "Test Point, Miniature, White, TH", Color=White, Manufacturer=Keystone, PartNumber=5002, Supplier Part Number 1=36-5002-ND
TP9: library part CMP-0055138-1, "Test Point, Miniature, Black, TH", Color=Black, Manufacturer=Keystone, PartNumber=5001, Supplier Part Number 1=36-5001-ND
TP10: library part CMP-0055137-1, "Test Point, Miniature, Red, TH", Color=Red, Manufacturer=Keystone, PartNumber=5000, Supplier Part Number 1=36-5000-ND
U1: library part CMP-0080714-4, "15-GHz Wideband PLLatinum™ RF Synthesizer With Phase Synchronization, RTC0048A (PVQFN-64)", Alternate Manufacturer="Texas Instruments"
Y1: library part CMP-0006121-3, "Crystal Oscillator, 100 MHz, LVDS, 3.3V, SMD", Frequency Stability=+/-25ppm, Manufacturer=Vectron, PartNumber=VC-708-EDE-FNXN-100M000000

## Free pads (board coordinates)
  round 120 smd paste-196.85: 1(1022.5,1200)

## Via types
v1: diameter 15, hole 8, Top Layer to Bottom Layer, tented both sides, 181 vias
v2: diameter 19.68, hole 11.81, Top Layer to Bottom Layer, tented both sides, 25 vias

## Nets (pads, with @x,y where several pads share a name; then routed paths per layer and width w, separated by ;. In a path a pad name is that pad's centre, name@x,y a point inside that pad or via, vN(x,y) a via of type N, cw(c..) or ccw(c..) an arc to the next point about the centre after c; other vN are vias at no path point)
CE: J1.2 TP1.1 U1.1 | length 1889.5
  Top Layer w10: v1(1631.5,1269.29) 1641.73,1279.53 U1.1@1641.73,1313.19
  Top Layer w20: TP1.1@176.57,1000 257.68,1081.1 257.68,1309.84 288.39,1340.55 540.55,1340.55 J1.2@600,1400 ; TP1.1@179.53,1000.2 TP1.1@179.72,1000
  Signal GND w10: J1.2@600,1400 660.04,1339.96 1022.44,1339.96 v1(1131.89,1230.51) v1@1131.89,1230.32
  Bottom Layer w10: v1(1131.89,1230.51) 1592.72,1230.51 v1(1631.5,1269.29)
CSB: C6.1 R6.2 TP2.1 U1.28 | length 1654.6
  Top Layer w10: U1.28@1799.21,1586.81 v1(1799.21,1613.98)
  Top Layer w20: R6.2@882.28,900 922.5,900 TP2.1@1022.5,1000
  Bottom Layer w10: TP2.1@1022.5,1000 1022.5,1551.83 1169.68,1699.02 1726.97,1699.02 1771.65,1654.33 C6.1@1771.65,1613.98 ; C6.1@1776.97,1611.22 C6.1@1776.97,1613.98
  Bottom Layer w20: C6.1@1776.97,1613.98 v1(1799.21,1613.98)
GND: C1.2 C1LF.2 C2.2 C3.2 C3LF.2 C4.2 C4LF.2 C5.2 C6.2 C7.2 C8.2 C9.2 C10.2 C11.2 C12.2 C13.2 C14.2 C15.2 C16.2 C17.2 C18.2 C19.2 C20.2 C21.2 C22.2 C23.2 C24.2 C25.2 C26.1 C29.1 C34.2 D1.2 J3.6 J4.2 J4.3 J4.4 J4.5 J5.2 J6.2 J6.3 J6.4 J6.5 J7.2 J7.3 J7.4 J7.5 J8.2 J8.3 J8.4 J9.2 J9.3 J9.4 J10.2 J10.3 J10.4 J12.2 J12.3 J12.4 J12.5 J13.2 J13.3 J13.4 J13.5 R2LF.1 R26.2 R27.2 R29.1 R30.1 R33.1 TP9.1 U1.2 U1.4 U1.6 U1.15 U1.16 U1.27 U1.29 U1.32 U1.40 U1.42 U1.47 U1.48 U1.49 Y1.3 | length 25476.6
  Top Layer w8: U1.48@1612.99,1341.73 1613.06,1341.8 1641.8,1341.8 1661.42,1361.42 v2(1671.26,1371.26) v2(1710.63,1410.63) v2(1750,1450) ; J9.3@2190.55,2091 J9.3@2190.55,2122.24
  Top Layer w10: U1.47@1613.19,1361.42 1661.42,1361.42 U1.2@1661.42,1313.19 ; U1.42@1613.19,1459.84 1665.16,1459.84 U1.49@1675,1450 ; U1.40@1613.19,1499.21 1660.79,1499.21 U1.49@1670,1490 ; U1.4@1700.79,1313.19 1700.79,1360.79 U1.49@1710,1370 ; U1.49@1710,1530 1720.47,1540.47 U1.32@1720.47,1586.81 ; U1.6@1740.16,1313.19 1740.16,1360.16 U1.49@1750,1370 ; U1.29@1779.53,1586.81 1779.53,1540.47 U1.49@1790,1530 ; v1(1813.19,703.74) Y1.3@1813.19,737.99 ; U1.27@1818.9,1586.81 1818.9,1541.1 U1.49@1830,1530 ; U1.49@1830,1370 1841.1,1381.1 U1.15@1886.81,1381.1 ; U1.49@1830,1410 1839.21,1400.79 U1.16@1886.81,1400.79 ; Y1.3@1839.37,730.91 Y1.3@1839.37,749.21
  Top Layer w12: v1@2129.92,1574.02 v1@2130.12,1574.21
  Top Layer w15: R26.2@1724.41,973.82 v1(1724.41,986.81) R29.1@1724.41,1012.99 ; R27.2@1854.33,964.57 v1(1854.33,986.81) R30.1@1854.33,1012.99
  Top Layer w20: D1.2@379.53,1300 v1(405.71,1300) ; C7.2@405.32,1652.36 C7.2@405.71,1651.97 v1(405.71,1621.85) ; C8.2@405.71,1866.14 v1@405.71,1896.06 ; J3.6@695,700 v1(775,700) v1(812.2,700) ; v1(788.39,1200) C9.2@818.5,1200 ; v1(788.39,1257.09) C10.2@818.5,1257.09 ; v1(1428.54,1343.7) C20.2@1443.7,1343.7 ; C21.2@1428.54,1452.76 v1(1428.54,1477.95) v1(1428.54,1558.27) C22.2@1428.54,1591.54 ; v1(1681.1,1104.92) C23.2@1681.1,1135.04 ; v1(1690.35,964.57) R26.2@1716.54,964.57 ; Y1.3@1812.99,738.19 Y1.3@1813.19,737.99 ; C26.1@1848.43,1804.53 v1(1848.43,1830.51) ; R27.2@1870.67,964.57 v1(1886.42,964.57) ; C29.1@2104.33,1509.06 v1(2130.51,1509.06) ; R33.1@2104.33,1574.02 v1@2129.92,1574.02
  RF GND w8: v2@1709.25,1450.59 1710.63,1451.97 v2(1710.63,1489.37) ; v2@1711.42,1489.37 v2(1750,1489.37) ; v2@1749.8,1409.84 1750,1410.04 v2(1750,1410.63) v2(1750,1450) ; v2@1750,1450.39 v2(1750,1489.37) ; v2@1750,1528.54 v2(1750,1489.37) ; v2@1750.2,1450.2 v2@1750.39,1450 ; v2@1789.37,1373.23 v2(1789.37,1410.63) ; v2@1789.37,1411.22 v2(1789.37,1450) 1828.54,1450 v2@1829.92,1448.62 ; v2@1789.37,1452.56 v2(1789.37,1489.37) ; v2@1790.55,1489.37 v2(1828.74,1489.37)
  RF GND w10: v1@1428.74,1343.7 1643.7,1343.7 v2(1671.26,1371.26) ; 1610.24,1343.11 1610.24,1300.39 1638.58,1300.39 1698.82,1240.16 1849.02,1240.16 1857.28,1248.43 v1(1857.28,1269.29)
  RF GND w20: 100,700 v1(300,700) ; v1(110,1650) v1(110,1868.11) ; v1@170.67,1962.6 170.08,1963.19 170.08,2070.08 251.38,2151.38 1000,2151.38 v1(1000,2100) 1000,2025 ; TP9.1@177.36,1201.97 177.95,1202.56 177.95,1300 178.35,1300 ; TP9.1@177.5,1200 90.55,1113.05 90.55,78.74 119.29,50 v1(240.94,50) v1(459.06,50) 520,50 ; 178.94,1299.41 178.35,1300 ; v1(300,350) v1(500,350) 500,700 ; v1(300,1000) 405.71,1000 ; v1(300,1556.55) 405.51,1556.69 405.71,1556.69 ; v1@300,1556.69 299.86,1556.55 v1(170,1556.55) 79.92,1466.48 79.92,1398.43 178.35,1300 ; v1(300,2100) 300,2150 ; 405.51,1555.12 405.71,1555.32 ; v1@405.71,1300.39 405.71,1555.32 ; v1(405.71,1621.85) 405.71,1556.69 ; v1(500,1500) v1(750,1500) v1(750,1750) v1(750,1925) v1(750,2100) 750,2150 ; v1(500,1925) v1(500,2100) 500,2150 ; 522.5,50 v1(740.94,50) v1(959.06,50) 1020,50 ; v1(788.39,1200) v1(788.39,1257.09) 645.87,1257.09 602.95,1300 v1(405.71,1300) 405.71,1000 ; v1@811.61,699.61 811.22,700 v1(775,700) 500,700 ; v1(900,1000) v1(700,1000) 405.71,1000 ; 1022.5,50 1125,50 ; v1(1125,750) v1(1125,550) v1(1125,350) 1125,50 ; v1(1250,1500) v1(1050,1500) 1000,1550 v1(1000,1750) v1(1000,1925) 1000,2025 ; v1(1250,2100) 1250,2025 ; v1(1330.12,1300.39) 1373.43,1343.7 v1(1428.54,1343.7) v1(1428.54,1387.01) v1@1428.54,1477.56 ; v1(1400,1000) v1(1400,750) v1(1400,550) v1(1400,350) 1400,313.78 1430.32,283.46 v1(1430.32,170) v1(1430.32,110) v1(1430.32,50) ; v1@1427.95,1343.31 1428.54,1342.72 1428.54,1261.02 v1(1525,1261.02) v1@1527.56,1261.02 ; v1(1428.54,1477.95) v1(1428.54,1558.27) v1@1428.54,1558.46 ; v1@1456.18,2075 1456.18,2027.49 v1@1457.48,2026.18 ; v1(1500,1750) v1(1250,1750) v1(1250,1925) 1250,2025 ; v1@1528.15,1261.02 1528.15,1142.32 1565.55,1104.92 1614.76,1104.92 ; v1@1556.43,1971.92 v1(1556.43,1925) 1639.96,1925 v1@1640.16,1925.2 ; v1@1556.43,1975 1556.43,2023.55 1557.87,2025 J8.3@1640.43,2025 v1(1742.13,2025) v1(1954.72,2025) J9.2@2056.43,2025 ; J8.2@1556.43,2025 v1(1454.72,2025) 1250,2025 ; v1(1681.1,1104.92) 1614.76,1104.92 ; v1@1740.68,2026.45 v1@1740.68,2075 ; v1(1813.19,703.74) v1(1868.11,703.74) 2077.17,703.74 ; v1(1848.43,1830.51) 1848.43,2024.41 1848.82,2024.8 ; v1@1875.59,550 v1(1875,550) ; v1@1884.25,964.57 v1(1690.35,964.57) 1614.76,1040.16 1614.76,1104.92 ; v1(1886.42,964.57) 2000,964.57 ; v1@1954.33,2125.79 1955.12,2125 J9.2@2056.43,2125 ; v1@1954.72,2025.86 v1(1954.72,2075) ; v1@1955.71,2025.39 v1@1956.18,2025.86 ; 2000,1150 2000,964.57 ; J9.2@2054.92,2024.02 2056.43,2022.51 v1(2056.43,1973.62) 2056.43,1927.63 v1@2057.09,1926.97 ; J9.2@2058.07,2025 J9.3@2140.43,2025 ; v1(2130.51,1509.06) 2324.8,1509.06 ; v1@2139.76,1925.39 2140.43,1926.06 v1(2140.43,1973.62) ; v1@2140.16,1974.02 2140.43,1974.28 J9.3@2140.43,2025 ; J9.3@2140.43,2125 2239.96,2125 v1@2240.55,2124.41 ; v1(2148.43,350) v1(2148.43,550) ; v1@2150,550 v1(2225,550) 2400,550 2400,1000 ; 2224.02,1802.76 2225.72,1801.06 2273.62,1801.06 ; v1@2226.18,1301.77 2225,1300.59 v1(2225,1217.06) 2272.12,1217.06 v1@2273.62,1215.55 ; v1@2242.13,2029.21 v1(2242.13,2075) ; 2274.02,1802.76 2275.72,1801.06 2325,1801.06 ; v1@2275,1217.06 2323.75,1217.06 J10.3@2324.8,1218.11 ; 2275,1717.06 2323.3,1717.06 2323.62,1716.73 ; 2291.54,2025 v1(2242.13,2025) J9.3@2140.43,2025 ; 2291.73,2024.8 2325,1991.54 2325,1801.06 ; 2325,1615.35 v1(2325,1402.76) J10.2@2325,1301.06 J10.3@2325,1217.06 v1(2325,1115.35) 2325,765.94 2262.8,703.74 2077.17,703.74 ; 2325,1617.52 2325,1717.06 ; 2325,1718.7 2325,1801.06 ; v1@2325.59,1402.17 2326.45,1401.3 v1@2375,1401.3 ; 2325.71,1616.81 2375,1616.81 ; 2325.71,1901.31 2375,1901.31 ; v1@2325.79,1117.72 2326.7,1116.8 v1@2375,1116.8 ; 2400,350 v1(2225,350) 2150,350 2148.43,348.43 v1(2148.43,170) v1(2148.43,110) v1(2148.43,50) v1(1930.32,50) 1930,50 1930,295 v1(1875,350) v1(1875,550) ; v1@2423.82,1117.13 2425,1118.31 J10.3@2425,1217.06 ; v1@2423.82,1403.35 2425,1402.17 J10.2@2425,1301.06 ; v1@2424.8,1903.74 2425,1903.54 v1(2425,1902.76) 2425,1801.06 ; 2425,1717.06 v1(2425,1615.35) 2425,1614.37 v1@2426.77,1612.6 ; 405.71,1000 405.71,719.29 425,700 500,700 ; 405.71,1555.32 405.71,1556.69 ; 1000,2025 1250,2025 ; 1125,50 v1(1430.32,50) ; v1(1430.32,50) v1(1648.43,50) v1(1648.43,110) v1(1648.43,170) 1648.43,283.07 1675,309.65 v1(1675,350) v1(1675,550) v1(1875,550) ; 2000,964.57 2039.96,964.57 2077.17,927.36 2077.17,703.74
  Bottom Layer w8: v2@1828.94,1489.76 1850.39,1489.76 C5.2@1857.28,1482.87
  Bottom Layer w10: C3LF.2@1639.76,1386.81 1647.44,1386.81 v2(1671.26,1410.63) ; C4LF.2@1644.29,1478.54 1643.5,1479.33 C2.2@1643.5,1563.98 C24.2@1686.61,1563.98 ; v2@1671.16,1528.64 v2@1671.26,1528.54 ; C24.2@1686.81,1563.98 C14.2@1730.12,1563.98 C6.2@1776.77,1563.98 ; C3.2@1720.47,1342.72 C18.2@1759.65,1342.72 ; C18.2@1763.78,1342.72 C19.2@1809.25,1342.72 ; C6.2@1776.97,1564.57 1836.22,1564.57 C13.2@1857.28,1543.5 C5.2@1857.28,1482.87 ; C19.2@1810.04,1342.72 C1LF.2@1857.28,1342.72 ; v1(1857.28,1269.29) C17.2@1857.28,1300.39 C1LF.2@1857.28,1342.72 ; C4.2@1857.28,1430.32 C16.2@1857.28,1387.01 C1LF.2@1857.28,1343.7 C1LF.2@1857.28,1342.72 ; C4.2@1857.28,1434.06 C5.2@1857.28,1482.09
  Bottom Layer w12: v1(2133.27,1701.77) C11.2@2112.06,1722.98 2152.36,1763.28 C12.2@2152.36,1763.39 v1(2173.62,1742.13)
  Bottom Layer w20: v1(1330.12,1300.39) R2LF.1@1356.3,1300.39 ; v1(1428.54,1558.27) C1.2@1454.72,1558.27 ; v1@1428.74,1387.01 C15.2@1446.85,1387.01 ; C34.2@1681.1,917.32 1681.1,955.51 v1@1690.16,964.57
  other v1: 240.94,110 459.06,110 740.94,109.84 959.06,110 1930.32,110 240.94,170 459.06,170 740.94,170 959.06,170 1930.32,170 2425,350 2425,550 2225,750 2425,750 2225,1000 2425,1000 1250,1104.92 2118.11,1115.35 2375,1115.35 2425,1115.35 1980.32,1217.32 2273.62,1217.06 2225,1301.06 2273.62,1301.06 2375,1402.76 2425,1402.76 50,1556.55 110,1556.55 2130.51,1574.02 2057.09,1615.35 2242.13,1615.35 50,1650 170,1650 50,1868.11 170,1868.11 405.71,1896.26 2242.13,1902.76 1640.43,1925 1850,1925 2056.43,1925 2140.43,1925 50,1961.56 110,1961.56 170,1961.56 1556.43,1973.62 1640.43,1973.62 1454.72,2075 1742.13,2075 1454.72,2125 1742.13,2125 1954.72,2125 2242.13,2125
  other v2: 1710.63,1371.26 1750,1371.26 1789.37,1371.26 1828.74,1371.26 1828.74,1410.63 1671.26,1450 1710.63,1450 1828.74,1450 1671.26,1489.37 1671.26,1528.74 1710.63,1528.74 1750,1528.74 1789.37,1528.74 1828.74,1528.74
MUXOUT: J2.1 J3.3 TP3.1 U1.23 | length 4991.8
  Top Layer w10: TP3.1@178.94,800.2 TP3.1@179.13,800 ; 378.74,798.43 378.74,800 ; U1.23@1886.81,1538.58 1906.5,1538.58 1916.54,1548.62 v1(1916.54,1570.87)
  Top Layer w20: TP3.1@179.13,800 378.74,800 ; J3.3@512.5,800 378.74,800 ; J2.1@600,1200 378.74,978.74 378.74,800
  Bottom Layer w10: TP3.1@177.5,800 82.68,705.18 82.68,336.22 140.55,278.35 2148.35,278.35 2187.4,317.4 2187.4,1400.95 2120.12,1468.23 1974.77,1468.23 1937.01,1505.99 1937.01,1565.35 1931.5,1570.87 v1(1916.54,1570.87) 1916.34,1570.87 v1@1916.14,1571.06 ; TP3.1@177.76,800.2 TP3.1@177.95,800 ; TP3.1@177.95,800.39 TP3.1@178.35,800
NetC1LF_1: C1LF.1 C2LF.1 R3LF.1 U1.14 | length 531.8
  Top Layer w10: U1.14@1892.91,1361.42 1917.72,1361.42
  Top Layer w20: 1919.29,1359.84 v1(1930.71,1348.43)
  Signal GND w10: v1(1586.61,1323.23) 1611.81,1348.43 1928.35,1348.43 v1@1930.71,1346.06
  Bottom Layer w20: C2LF.1@1511.22,1300.39 1563.78,1300.39 v1(1586.61,1323.23) 1586.61,1342.32 R3LF.1@1587.99,1343.7 ; C1LF.1@1903.35,1343.5 1925.79,1343.5 v1(1930.71,1348.43)
NetC2LF_2: C2LF.2 R2LF.2 | length 51.5
  Bottom Layer w20: R2LF.2@1403.54,1300.39 C2LF.2@1454.72,1300.39 C2LF.2@1454.92,1300.2
NetC3LF_1: C3LF.1 R3LF.2 R4LF.1 | length 117.8
  Bottom Layer w8: C3LF.1@1592.32,1387.01 C3LF.1@1593.37,1387.01 ; R4LF.1@1630.51,1424.61 1630.51,1424.15 C3LF.1@1593.37,1387.01 ; R3LF.2@1638.58,1342.32 1638.05,1342.32 C3LF.1@1593.37,1387.01
NetC4LF_1: C4LF.1 R4LF.2 U1.43 | length 142.4
  Top Layer w10: 1577.56,1440.16 U1.43@1613.19,1440.16
  Top Layer w20: v1(1566.73,1456.69) 1578.35,1445.08
  Bottom Layer w8: R4LF.2@1592.32,1430.32 R4LF.2@1602.76,1430.32 ; R4LF.2@1603.94,1430.91 C4LF.1@1603.94,1473.62
  Bottom Layer w20: v1(1566.73,1456.69) 1566.73,1466.14 1574.41,1473.82 ; C4LF.1@1577.17,1474.02 C4LF.1@1594.09,1474.02
NetC13_1: C13.1 R13.2 U1.24 | length 132.3
  Top Layer w20: U1.24@1886.81,1562.99 v1(1886.81,1574.21)
  Bottom Layer w12: 1882.87,1565.16 C13.1@1904.53,1543.5 ; 1886.81,1561.22 v1(1886.81,1574.21)
  Bottom Layer w20: v1(1886.81,1574.21) 1886.81,1586.81 R13.2@1932.68,1632.68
